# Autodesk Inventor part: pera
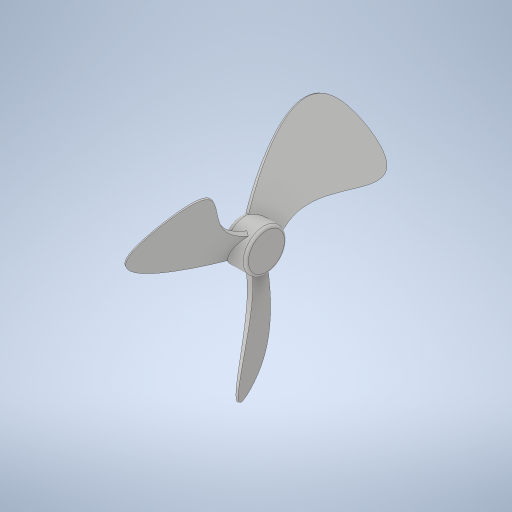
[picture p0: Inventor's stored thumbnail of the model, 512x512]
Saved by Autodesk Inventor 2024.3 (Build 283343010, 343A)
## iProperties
Created: 2021-06
Part Number: pera
Material: 一般
Document SubType Name: Modeling
Designer: kikut
Density: 1 g/cm^3
Appearance: 既定
Mass: 37.2793 g
Surface Area: 276.029 cm^2
Volume: 37.2793 cm^3
Author: kikut
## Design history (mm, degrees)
sketch "スケッチ1"
  geometry: L1 (21.732, -33.641)-(-18.268, 35.641); L2 (-18.268, 35.641)-(-21.732, 33.641); L3 (-21.732, 33.641)-(18.268, -35.641); L4 (18.268, -35.641)-(21.732, -33.641); L5 (21.732, -33.641)-(-21.732, 33.641); L6 (-18.268, 35.641)-(18.268, -35.641); L7 (30.425, 0)-(-30.425, 0) reference; 1 further point
  constraints: 12 end point, 2 midpoint, 2 parallel, 1 perpendicular
  dimensions: "d0" = 60 deg angle of L3 L7; "d1" = 4 distance of L1.end L2.end; "d2" = 80 distance of L1.start L1.end
extrude "押し出し1" new body sketch "スケッチ1" distance "d3" = 100; taper "d4" = -1 deg
sketch "スケッチ2"
  geometry: L1 (0, 0)-(80, 0) reference; L2 (1.746, -100.015)-(78.254, -100.015) reference; L3 (0, 0)-(1.746, -100.015) reference; L4 (80, 0)-(78.254, -100.015) reference; L5 (47.995, 0)-(32.005, 0); L6 (100, 20)-(-20, 20); L7 (-20, 20)-(-20, -130); L8 (-20, -130)-(100, -130); L9 (100, -130)-(100, 20); 7 further points
  constraints: 10 end point, 2 parallel, 2 point on line, 1 collinear, 1 horizontal, 1 perpendicular, 8 other
  dimensions: "d5" = 8 distance from line of L2 point (48.39, -92.015); "d7" = 32 distance from line of L5.start L4; "d8" = 32 distance from line of L5.end L3; "d9" = 10 distance from line of L3 point (10.804, -46); "d10" = 46 distance from line of L1 point (10.804, -46); "d11" = 22 distance from line of point (57.124, -50) L4; "d12" = 4 distance from line of point (74.603, -80.015) L4; "d13" = 20 distance from line of point (74.603, -80.015) L2; "d14" = 50 distance from line of L1 point (57.124, -50); "d17" = 12 distance from line of point (13.503, -86.015) L3; "d18" = 20 distance between parallel lines of L1 L6; "d19" = 20 distance from line of L1.start L7; "d20" = 20 distance from line of L1.end L9; "d21" = 150 distance of L8.end L6.start; "d27" = 14 distance from line of L2 point (13.503, -86.015); "d28" = 32 distance from line of L4 point (47.681, -18); "d29" = 30 distance from line of point (48.39, -92.015) L4; "d34" = 18 distance from line of L1 point (47.681, -18)
extrude "押し出し2" cut sketch "スケッチ2" distance "d22" = 100; taper "d23" = 0 deg
pattern_circular "円形状パターン1" dims "d25" = 360 deg
sketch "スケッチ3"
  geometry: L1 (0, -5.924)-(0, 0) reference; C1 r 16 at (0, 0)
  constraints: 1 centre point, 1 coincident
  dimensions: "d30" = 32 diameter of C1
extrude "押し出し3" join sketch "スケッチ3" stored distance "d31" = 20; taper "d32" = 0 deg
fillet "フィレット1" dims "d33" = 4
fillet "フィレット2" dims "d35" = 2
node "ソリッド1"
